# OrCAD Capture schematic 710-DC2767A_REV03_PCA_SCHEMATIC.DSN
size Custom; note: HIGH SPEED COMPARATOR WITH LVDS OUTPUT
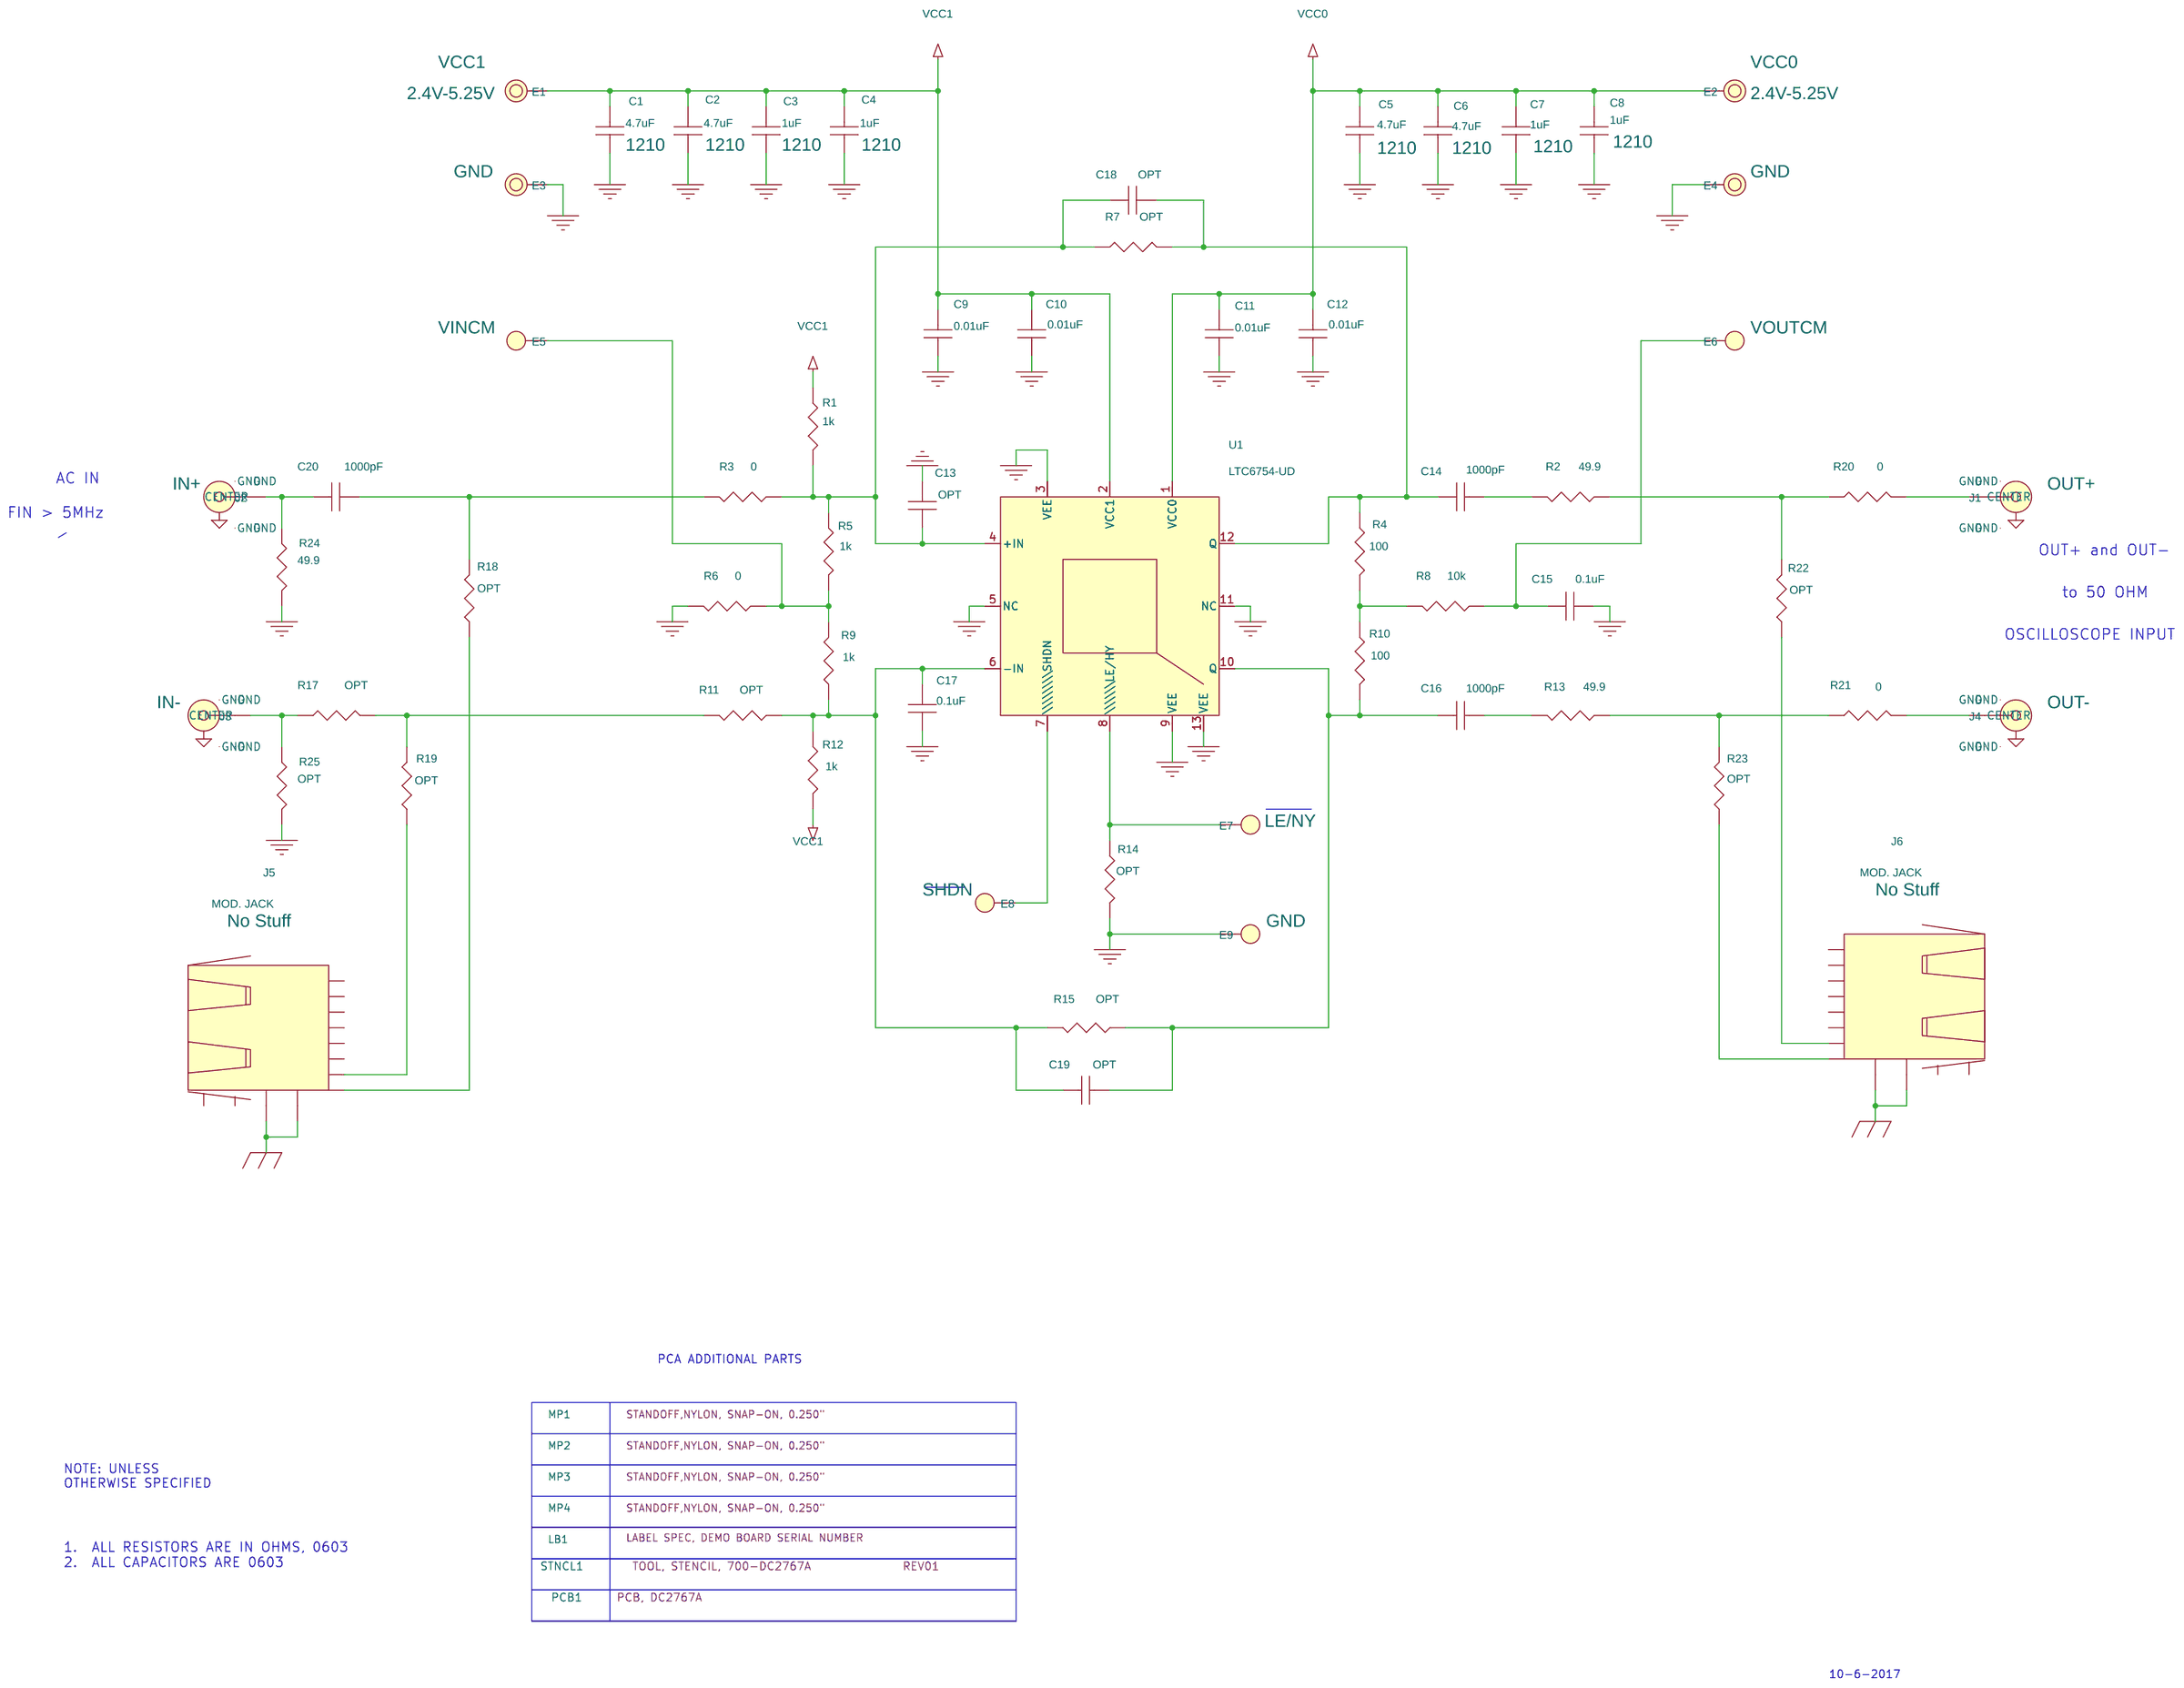
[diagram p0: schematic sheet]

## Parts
C1  4.7uF  [CC1210N]
C2  4.7uF  [CC1210N]
C3  1uF  [CC1210N]
C4  1uF  [CC1210N]
C5  4.7uF  [CC1210N]
C6  4.7uF  [CC1210N]
C7  1uF  [CC1210N]
C8  1uF  [CC1210N]
C9  0.01uF  [CC0603N]
C10  0.01uF  [CC0603N]
C11  0.01uF  [CC0603N]
C12  0.01uF  [CC0603N]
C13  OPT  [CC0603N]
C14  1000pF  [CC0603N]
C15  0.1uF  [CC0603N]
C16  1000pF  [CC0603N]
C17  0.1uF  [CC0603N]
C18  OPT  [CC0603N]
C19  OPT  [CC0603N]
C20  1000pF  [CC0603N]
E1  TEST POINT  [MILLMAX2501]
E2  TEST POINT  [MILLMAX2501]
E3  TEST POINT  [MILLMAX2501]
E4  TEST POINT  [MILLMAX2501]
E5  TEST POINT  [MILLMAX2308]
E6  TEST POINT  [MILLMAX2308]
E7  TEST POINT  [MILLMAX2308]
E8  TEST POINT  [MILLMAX2308]
E9  TEST POINT  [MILLMAX2308]
J1  SMA  [EMERSON_142-0701-851]
J2  SMA  [EMERSON_142-0701-851]
J3  SMA  [EMERSON_142-0701-851]
J4  SMA  [EMERSON_142-0701-851]
J5  MOD. JACK  [CON-RJ45-5406298]
J6  MOD. JACK  [CON-RJ45-5406298]
LB1  LABEL  [895-0154_REV01]
MP1  STANDOFF  [MTG-8831]
MP2  STANDOFF  [MTG-8831]
MP3  STANDOFF  [MTG-8831]
MP4  STANDOFF  [MTG-8831]
PCB1  PCB, DC2767A
R1  1k  [CR0603N]
R2  49.9  [CR0603N]
R3  0  [CR0603N]
R4  100  [CR0603N]
R5  1k  [CR0603N]
R6  0  [CR0603N]
R7  OPT  [CR0603N]
R8  10k  [CR0603N]
R9  1k  [CR0603N]
R10  100  [CR0603N]
R11  OPT  [CR0603N]
R12  1k  [CR0603N]
R13  49.9  [CR0603N]
R14  OPT  [CR0603N]
R15  OPT  [CR0603N]
R17  OPT  [CR0603N]
R18  OPT  [CR0603N]
R19  OPT  [CR0603N]
R20  0  [CR0603N]
R21  0  [CR0603N]
R22  OPT  [CR0603N]
R23  OPT  [CR0603N]
R24  49.9  [CR0603N]
R25  OPT  [CR0603N]
STNCL1  TOOL, STENCIL, 700-DC2650A
U1  LTC6754-UD  [LTC-UD-12-1855]

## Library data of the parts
C1 C2 C5 C6 = CAP: CAP.,4.7uF,X7R,50V,10%,1210; CLASS: DISCRETE; Dielectric Type: X7R; FPLIST: CC1210N,CC1210L,CC1210M; Manufacturer: MURATA; Manufacturer PN: GRM32ER71H475KA88L; PART_NUMBER: 150-3088; Package Size: 1210; Rated Voltage: 50V; Tolerance: 10%
C3 C4 C7 C8 = CAP: CAP.,1uF,X5R,50V,10%,1210; CLASS: DISCRETE; Dielectric Type: X5R; FPLIST: CC1210N,CC1210L,CC1210M; Manufacturer: NIC; Manufacturer PN: NMC1210X5R105K50TRPLPF; PART_NUMBER: 150-0359; Package Size: 1210; Rated Voltage: 50V; Tolerance: 10%
C9-C12 = CAP: CAP.,0.01uF,X7R,25V,10%,0603; CLASS: DISCRETE; Dielectric Type: X7R; FPLIST: CC0603N,CC0603L,CC0603M; Manufacturer: SAMSUNG; Manufacturer PN: CL10B103KA8NNNC; PART_NUMBER: 150-3225; Package Size: 0603; Rated Voltage: 25V; Tolerance: 10%
C13 C18 C19 = CAP: CAP., OPTION, 0603; CLASS: DISCRETE; FPLIST: CC0603N,CC0603L,CC0603M; PART_NUMBER: 150-3038; Package Size: 0603; Package Type: SMD; UserField01: OPTION
C14 C16 C20 = CAP: CAP.,1000pF,X7R,50V,10%,0603; CLASS: DISCRETE; Dielectric Type: X7R; FPLIST: CC0603N,CC0603L,CC0603M; Manufacturer: AVX; Manufacturer PN: 06035C102KAT2A; PART_NUMBER: 150-3027; Package Size: 0603; Rated Voltage: 50V; Tolerance: 10%
C15 C17 = CAP: CAP.,0.1uF,X7R,16V,10%,0603; CLASS: DISCRETE; Dielectric Type: X7R; FPLIST: CC0603N,CC0603L,CC0603M; Manufacturer: AVX; Manufacturer PN: 0603YC104KAT2A; PART_NUMBER: 150-0164; Package Size: 0603; Package Type: SMD; Rated Voltage: 16V; Tolerance: 10%
E1 = TESTPOINT_.219_MILL-MAX_2501: TEST POINT,TURRET,0.094",MTG. HOLE; 1: VCC1; 2: 2.4V-5.25V; CLASS: IO; FPLIST: MILLMAX2501,MILLMAX2501_ALT1; Manufacturer: MILL-MAX; Manufacturer PN: 2501-2-00-80-00-00-07-0; PART_NUMBER: 260-0003
E2 = TESTPOINT_.219_MILL-MAX_2501: TEST POINT,TURRET,0.094",MTG. HOLE; 1: VCC0; 2: 2.4V-5.25V; CLASS: IO; FPLIST: MILLMAX2501,MILLMAX2501_ALT1; Manufacturer: MILL-MAX; Manufacturer PN: 2501-2-00-80-00-00-07-0; PART_NUMBER: 260-0003
E3 E4 = TESTPOINT_.219_MILL-MAX_2501: TEST POINT,TURRET,0.094",MTG. HOLE; 1: GND; 2: GND; CLASS: IO; FPLIST: MILLMAX2501,MILLMAX2501_ALT1; Manufacturer: MILL-MAX; Manufacturer PN: 2501-2-00-80-00-00-07-0; PART_NUMBER: 260-0003
E5 = TEST_POINT_.156_MILL-MAX_2308: TEST POINT,TURRET,0.064",MTG. HOLE; 1: VINCM; 2: VINCM; CLASS: IO; Manufacturer: MILL-MAX; Manufacturer PN: 2308-2-00-80-00-00-07-0; PART_NUMBER: 260-0004
E6 = TEST_POINT_.156_MILL-MAX_2308: TEST POINT,TURRET,0.064",MTG. HOLE; 1: VOUTCM; 2: 2.4V-5.25V; CLASS: IO; Manufacturer: MILL-MAX; Manufacturer PN: 2308-2-00-80-00-00-07-0; PART_NUMBER: 260-0004
E7 = TEST_POINT_.156_MILL-MAX_2308: TEST POINT,TURRET,0.064",MTG. HOLE; 1: LE/NY; CLASS: IO; Manufacturer: MILL-MAX; Manufacturer PN: 2308-2-00-80-00-00-07-0; PART_NUMBER: 260-0004
E8 = TEST_POINT_.156_MILL-MAX_2308: TEST POINT,TURRET,0.064",MTG. HOLE; 1: SHDN; CLASS: IO; Manufacturer: MILL-MAX; Manufacturer PN: 2308-2-00-80-00-00-07-0; PART_NUMBER: 260-0004
E9 = TEST_POINT_.156_MILL-MAX_2308: TEST POINT,TURRET,0.064",MTG. HOLE; 1: GND; CLASS: IO; Manufacturer: MILL-MAX; Manufacturer PN: 2308-2-00-80-00-00-07-0; PART_NUMBER: 260-0004
J1 = CONN_SMA_5PIN: CONN.,SMA,JACK, RCPT,END LAUNCH, STR,50 OHMS; 1: OUT+; CLASS: IO; FPLIST: EMERSON_142-0701-851,SMA-CINCH-142-0761-881_142-0701-851; Manufacturer: CINCH/ BEL; Manufacturer PN: 142-0701-851; PART_NUMBER: 250-0446
J2 = CONN_SMA_5PIN: CONN.,SMA,JACK, RCPT,END LAUNCH, STR,50 OHMS; 1: IN+; CLASS: IO; FPLIST: EMERSON_142-0701-851,SMA-CINCH-142-0761-881_142-0701-851; Manufacturer: CINCH/ BEL; Manufacturer PN: 142-0701-851; PART_NUMBER: 250-0446
J3 = CONN_SMA_5PIN: CONN.,SMA,JACK, RCPT,END LAUNCH, STR,50 OHMS; 1: IN-; CLASS: IO; FPLIST: EMERSON_142-0701-851,SMA-CINCH-142-0761-881_142-0701-851; Manufacturer: CINCH/ BEL; Manufacturer PN: 142-0701-851; PART_NUMBER: 250-0446
J4 = CONN_SMA_5PIN: CONN.,SMA,JACK, RCPT,END LAUNCH, STR,50 OHMS; 1: OUT-; CLASS: IO; FPLIST: EMERSON_142-0701-851,SMA-CINCH-142-0761-881_142-0701-851; Manufacturer: CINCH/ BEL; Manufacturer PN: 142-0701-851; PART_NUMBER: 250-0446
J5 J6 = JACK_RJ45_SHIELDED: CONN.,MOD. JACK,FEMALE,8 POS,R/A, THT,SINGLE PORT, SHIELDED; BOM Notes: No Stuff; CLASS: IO; Manufacturer: TE CONNECTIVITY; Manufacturer PN: 5406298-1; PART_NUMBER: 250-0488
LB1 = BLANK_LABEL: LABEL SPEC, DEMO BOARD SERIAL NUMBER; Manufacturer: BRADY; Manufacturer PN: THT-96-717-10; PART_NUMBER: 895-0154
MP1-MP4 = BLANK_MECHANICAL_PART: STANDOFF,NYLON, SNAP-ON, 0.250"; CLASS: MECHANICAL PART; Manufacturer: KEYSTONE; Manufacturer PN: 8831; PART_NUMBER: 763-0006
PCB1 = BLANK_PCB_PART: CLASS: DISCRETE; Manufacturer: MAO BANG; Manufacturer PN: 600-DC2767A; PART_NUMBER: 600-DC2767A
R1 R5 R9 R12 = RES: RES.,1k OHMS,1%,1/10W,0603; CLASS: DISCRETE; FPLIST: CR0603N,CR0603L,CR0603M; Manufacturer: NIC; Manufacturer PN: NRC06F1001TRF; PART_NUMBER: 100-2422; Package Size: 0603; Rated Power: 1/10W; Temperature Coefficient: 100ppm; Tolerance: 1%
R2 R13 = RES: RES.,49.9 OHMS,1%,1/10W,0603; CLASS: DISCRETE; FPLIST: CR0603N,CR0603L,CR0603M; Manufacturer: YAGEO; Manufacturer PN: RC0603FR-0749R9L; PART_NUMBER: 100-0115; Package Size: 0603; Rated Power: 1/10W; Tolerance: 1%
R3 R6 R20 R21 = RES: RES.,0 OHM,1/10W,0603; CLASS: DISCRETE; FPLIST: CR0603N,CR0603L,CR0603M; Manufacturer: VISHAY; Manufacturer PN: CRCW06030000Z0EA; PART_NUMBER: 100-0009; Package Size: 0603; Rated Power: 1/10W
R4 R10 = RES: RES.,100 OHMS,1%,1/10W,0603; CLASS: DISCRETE; FPLIST: CR0603N,CR0603L,CR0603M; Manufacturer: NIC; Manufacturer PN: NRC06F1000TRF; PART_NUMBER: 100-2586; Package Size: 0603; Rated Power: 1/10W; Temperature Coefficient: 100ppm; Tolerance: 1%
R7 R11 R14 R15 R17-R19 R22 R23 R25 = RES: RES., OPTION, 0603; CLASS: DISCRETE; FPLIST: CR0603N,CR0603L,CR0603M; PART_NUMBER: 100-2374; Package Size: 0603
R8 = RES: RES.,AEC-Q200,10k OHMS,1%,1/10W,0603; CLASS: DISCRETE; FPLIST: CR0603N,CR0603L,CR0603M; Manufacturer: KOA SPEER; Manufacturer PN: RK73H1JTTD1002F; PART_NUMBER: 100-2012; Package Size: 0603; Rated Power: 1/10W; Temperature Coefficient: +/-100ppm/C; Tolerance: 1%
R24 = RES: RES.,49.9 OHMS,1%,1/10W,0603; CLASS: DISCRETE; FPLIST: CR0603N,CR0603L,CR0603M; Manufacturer: VISHAY; Manufacturer PN: CRCW060349R9FKEA; PART_NUMBER: 100-0167; Package Size: 0603; Rated Power: 1/10W; Temperature Coefficient: 100ppm; Tolerance: 1%
STNCL1 = BLANK_STENCIL_PART: TOOL, STENCIL, 700-DC2767A; BOM Notes: REV01; CLASS: DISCRETE; Manufacturer: LINEAR TECHNOLOGY; Manufacturer PN: 830-DC2650A; PART_NUMBER: 830-DC2650A
U1 = LTC6754-UD: IC,HIGH SPEED RAIL-TO-RAIL, INPUT COMPARATOR WITH LVDS COMPATIBLE OUTPUTS; CLASS: IC; Manufacturer: LINEAR TECH.; Manufacturer PN: LTC6754IUD#PBF; PART_NUMBER: LTC6754IUD#PBF; Package Type: ??

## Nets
GND: C1.1 C2.1 C3.1 C4.1 C5.1 C6.1 C7.1 C8.1 C9.1 C10.1 C11.1 C12.1 C13.2 C15.2 C17.1 E3.1 E4.1 E9.1(A) J1.2(GND) J1.3(GND) J1.4(GND) J1.5(GND) J2.2(GND) J2.3(GND) J2.4(GND) J2.5(GND) J3.2(GND) J3.3(GND) J3.4(GND) J3.5(GND) J4.2(GND) J4.3(GND) J4.4(GND) J4.5(GND) R6.2 R14.2 R24.2 R25.2 U1.3(VEE) U1.5(NC) U1.9(VEE) U1.11(NC) U1.13(VEE)
GND_EARTH: J5.S1 J5.S2 J6.S1 J6.S2
VCC0: C5.2 C6.2 C7.2 C8.2 C11.2 C12.2 E2.1 U1.1(VCC0)
VCC1: C1.2 C2.2 C3.2 C4.2 C9.2 C10.2 E1.1 R1.1 R12.2 U1.2(VCC1)
N17501904: C17.2 C19.1 R9.1 R11.1 R12.1 R15.2 U1.6(-IN)
N17501919: C13.1 C18.1 R1.2 R3.1 R5.1 R7.1 U1.4(+IN)
N17502553: E5.1(A) R5.2 R6.1 R9.2
N17503453: C14.1 C18.2 R4.1 R7.2 U1.12(Q)
N17503462: C16.1 C19.2 R10.2 R15.1 U1.10(Q)
N17503484: R4.2 R8.2 R10.1
N17503594: C16.2 R13.2
N17503597: C14.2 R2.2
N17503600: C15.1 E6.1(A) R8.1
N17504290: E7.1(A) R14.1 U1.8(\\\\\\LE/HY)
N17506091: E8.1(A) U1.7(\\\\\\\\SHDN)
N17511863: J3.1(CENTER) R17.1 R25.1
N17511866: C20.2 R3.2 R18.2
N17511882: R11.2 R17.2 R19.2
N17511887: J5.1 R18.1
N17511892: J5.2 R19.1
N17512072: J6.2 R22.1
N17512078: R2.1 R20.1 R22.2
N17512088: J1.1(CENTER) R20.2
N17512091: J4.1(CENTER) R21.2
N17512094: R13.1 R21.1 R23.2
N17534546: C20.1 J2.1(CENTER) R24.1
N17537618: J6.1 R23.1

Not connected (* = marked no-connect by the designer): J5 3 4 5 6 7 8; J6 3 4 5 6 7 8

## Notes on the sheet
- AC IN
- FIN > 5MHz
- OUT+ and OUT-
- to 50 OHM
- OSCILLOSCOPE INPUT
- PCA ADDITIONAL PARTS
- NOTE: UNLESS
  OTHERWISE SPECIFIED
- 1.  ALL RESISTORS ARE IN OHMS, 0603
  2.  ALL CAPACITORS ARE 0603
- 10-6-2017
